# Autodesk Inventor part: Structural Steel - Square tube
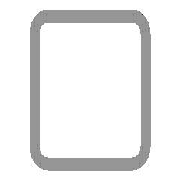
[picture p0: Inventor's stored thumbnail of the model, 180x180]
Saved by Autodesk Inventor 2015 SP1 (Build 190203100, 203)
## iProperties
IsCustomPart: 1
Created: 2011-02
Part Number: Structural Steel - Square tube
Material: Stainless Steel
Document SubType Name: Modeling
Standard: ISO
Designer: Guilherme Augusto Franco de Souza
Standard Revision: Second edition 2001-09-01
Standards Organization: ISO
Language: en-US
Size Designation: 25x25x2
Categories: <MemberInstance><Categories><Category DisplayName="Structural Shapes" InternalName="089c4875-fa83-4c05-b084-43b9cc11f5ed" Mnemonic="GRDR"><CategoryParameter Dis
Stock Number: 25x25x2
Density: 8.08 g/cm^3
Description: ISO 4019 - 25x25x2
Appearance: Steel
G_L: 390,000 mm
G_W: 25,000 mm
G_H: 25,000 mm
+B89455D9-CC8F-490E-ADB0-AB19616D39C9+CUTDETAIL1: Miter 45,00 deg
+0F80EDEF-A486-4730-8E53-CB40EEA5F8AB+CUTDETAIL2: Miter 45,00 deg
Author: Guilherme Augusto Franco de Souza
_CCFamilyMember: 2
_CCFamilyDisplayName: ISO 4019 (Square) - Structural steels - Cold-formed, welded, structural hollow sections
_FrameMemberDoc: Frame Member File
_Version: 15.0.0
_GetPNFromCC: 1
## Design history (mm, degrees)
node "Start plane"
node "End plane"
sketch "Sketch"
  geometry: L1 (-12.5, -8.5)-(-12.5, 8.5); L2 (-8.5, 12.5)-(8.5, 12.5); L3 (12.5, 8.5)-(12.5, -8.5); L4 (8.5, -12.5)-(-8.5, -12.5); L5 (-8.5, 10.5)-(8.5, 10.5); L6 (10.5, 8.5)-(10.5, -8.5); L7 (8.5, -10.5)-(-8.5, -10.5); L8 (-10.5, -8.5)-(-10.5, 8.5); L9 (0, 18.66)-(0, -18.66) reference; L10 (-18.66, 0)-(18.66, 0) reference; A1 r 4 centre (-8.5, -8.5) between (-12.5, -8.5) and (-8.5, -12.5); A2 r 4 centre (8.5, 8.5) between (12.5, 8.5) and (8.5, 12.5); A3 r 4 centre (-8.5, 8.5) between (-8.5, 12.5) and (-12.5, 8.5); A4 r 4 centre (8.5, -8.5) between (8.5, -12.5) and (12.5, -8.5); A5 r 2 centre (-8.5, 8.5) between (-8.5, 10.5) and (-10.5, 8.5); A6 r 2 centre (8.5, 8.5) between (10.5, 8.5) and (8.5, 10.5); A7 r 2 centre (8.5, -8.5) between (8.5, -10.5) and (10.5, -8.5); A8 r 2 centre (-8.5, -8.5) between (-10.5, -8.5) and (-8.5, -10.5)
  constraints: 16 end point, 16 point on circle, 8 centre point, 8 tangent, 4 parallel, 3 equal radius, 2 perpendicular, 7 other
  dimensions: "d7" = 4 radius of A1 (= G_IR); "d9" = 25 distance between parallel lines of L1 L3 (= G_W); "d11" = 25 distance between parallel lines of L2 L4 (= G_H); "d12" = 2 distance between parallel lines of L3 L6 (= G_T); "d15" = 12.5 distance between parallel lines of L9 L3 (= 0.5 x d9); "d16" = 12.5 distance between parallel lines of L2 L10 (= 0.5 x d11)
extrude "Body" new body sketch "Sketch" stored distance "d3" = 390 (= G_L); taper "d4" = 0 deg
node "Driven Length"
  sketch "Sketch3"
    geometry: L1 (0, 0)-(10, 0) reference
    constraints: 2 end point, 1 horizontal
  workplane "Work Plane3"
  sketch "Sketch4"
    geometry: L1 (-2, 0.141)-(12, 0.141) reference; L2 (-2, 389.859)-(12, 389.859) reference
    dimensions: "d18" = 389.71716 distance between parallel lines of L1 L2 (derived)
workplane "Work Plane4"
split "Split1"
workplane "Work Plane5"
split "Split2"
body "Solid1"
other parameters: "G_W" = 25 [user parameter; used in 1 equation term], "G_H" = 25 [user parameter; used in 1 equation term], "G_T" = 2 [user parameter; used in 1 equation term], "G_IR" = 4 [user parameter; used in 1 equation term], "G_L" = 390 [user parameter; used in 1 equation term], "G_OFFSET_START" = -0.14142 [user parameter; used in 1 equation term], "G_OFFSET_END" = -0.14142 [user parameter; used in 1 equation term], "d13" = 0.14142 (= -G_OFFSET_START), "d14" = 389.85858 (= G_OFFSET_END + B_L), "d17" = 90 deg, "MAS" = 0.136 [user parameter]
